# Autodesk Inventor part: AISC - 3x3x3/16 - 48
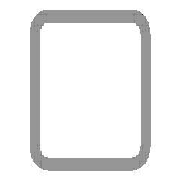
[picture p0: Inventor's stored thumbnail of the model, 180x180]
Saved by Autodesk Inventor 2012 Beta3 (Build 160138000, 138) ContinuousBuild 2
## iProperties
IsCustomPart: 1
Created: 2011-01
Part Number: AISC - 3x3x3/16 - 48
Material: Steel, Mild
Description: Tube
Document SubType Name: Modeling
Standard: ANSI
Designer: Beta-8540w
Standards Organization: ANSI
Language: en-US
Size Designation: 3x3x3/16
Categories: <MemberInstance><Categories><Category DisplayName="Structural Shapes" InternalName="089c4875-fa83-4c05-b084-43b9cc11f5ed" Mnemonic="GRDR"><CategoryParameter Dis
Stock Number: 3x3x3/16
Density: 7.86 g/cm^3
_CCFamilyMember: 9
_CCFamilyDisplayName: ANSI AISC (Square) - Tube
_FrameMemberDoc: Frame Member File
_Version: 15.0.0
_GetPNFromCC: 1
G_L: 48.000 in
G_W: 3.000 in
G_H: 3.000 in
Author: Beta-8540w
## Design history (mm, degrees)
node "Start plane"
node "End plane"
sketch "Sketch"
  geometry: L1 (-38.1, -28.575)-(-38.1, 28.575); L2 (-28.575, 38.1)-(28.575, 38.1); L3 (38.1, 28.575)-(38.1, -28.575); L4 (28.575, -38.1)-(-28.575, -38.1); L5 (-28.575, 33.337)-(28.575, 33.338); L6 (33.338, 28.575)-(33.338, -28.575); L7 (28.575, -33.337)-(-28.575, -33.338); L8 (-33.338, -28.575)-(-33.338, 28.575); L9 (0, 56.102)-(0, -56.102) reference; L10 (-56.102, 0)-(56.102, 0) reference; A1 r 9.525 centre (-28.575, -28.575) between (-38.1, -28.575) and (-28.575, -38.1); A2 r 9.525 centre (-28.575, 28.575) between (-28.575, 38.1) and (-38.1, 28.575); A3 r 9.525 centre (28.575, 28.575) between (38.1, 28.575) and (28.575, 38.1); A4 r 9.525 centre (28.575, -28.575) between (28.575, -38.1) and (38.1, -28.575); A5 r 4.763 centre (-28.575, 28.575) between (-28.575, 33.337) and (-33.338, 28.575); A6 r 4.763 centre (28.575, 28.575) between (33.338, 28.575) and (28.575, 33.338); A7 r 4.763 centre (28.575, -28.575) between (28.575, -33.337) and (33.338, -28.575); A8 r 4.763 centre (-28.575, -28.575) between (-33.338, -28.575) and (-28.575, -33.338)
  constraints: 16 end point, 16 point on circle, 8 centre point, 8 tangent, 4 parallel, 3 equal radius, 2 perpendicular, 7 other
  dimensions: "d10" = 76.2 distance between parallel lines of L2 L4 (= G_H); "d11" = 76.2 distance between parallel lines of L1 L3 (= G_W); "d12" = 4.7625 distance between parallel lines of L3 L6 (= G_T); "d15" = 38.1 distance between parallel lines of L2 L10 (= 0.5 x d10); "d16" = 38.1 distance between parallel lines of L9 L3 (= 0.5 x d11); "d17" = 9.525 radius of A1 (= G_IR)
extrude "Body" new body sketch "Sketch" stored distance "d3" = 1219.2 (= G_L); taper "d4" = 0 deg
node "Driven Length"
  sketch "Sketch3"
    geometry: L1 (0, 0)-(10, 0) reference
    constraints: 2 end point, 1 horizontal
  workplane "Work Plane3"
  sketch "Sketch4"
    geometry: L1 (-2, 0)-(12, 0) reference; L2 (-2, 1219.2)-(12, 1219.2) reference
    dimensions: "d19" = 1219.2 distance between parallel lines of L1 L2 (derived)
body "Solid1"
other parameters: "G_W" = 76.2 [user parameter; used in 1 equation term], "G_H" = 76.2 [user parameter; used in 1 equation term], "G_T" = 4.7625 [user parameter; used in 1 equation term], "G_IR" = 9.525 [user parameter; used in 1 equation term], "G_L" = 1219.2 (= d19) [user parameter; used in 1 equation term], "G_OFFSET_START" = 0 [user parameter; used in 1 equation term], "G_OFFSET_END" = 0 [user parameter; used in 1 equation term], "d13" = 0 (computed from G_OFFSET_START), "d14" = 1219.2 (= G_OFFSET_END + B_L), "B_L" = 1219.2 [user parameter; used in 1 equation term], "d18" = 90 deg
